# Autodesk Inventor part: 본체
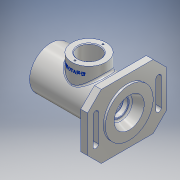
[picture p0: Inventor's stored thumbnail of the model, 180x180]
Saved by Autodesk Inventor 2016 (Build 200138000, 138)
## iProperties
Created: 2017-10
Part Number: 본체
Material: 알루미늄 6061
Document SubType Name: Modeling
Designer: USER
Density: 2.7 g/cm^3
Appearance: 알루미늄 - 평지
Mass: 735.583 g
Surface Area: 651.612 cm^2
Volume: 272.438 cm^3
Author: USER
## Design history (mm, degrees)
sketch "스케치1"
  geometry: L1 (-38, 47)-(38, 47); L2 (58, 27)-(58, -27); L3 (38, -47)-(-38, -47); L4 (-58, -27)-(-58, 27); L5 (-38, 47)-(-58, 27); L6 (38, 47)-(58, 27); L7 (-58, -27)-(-38, -47); L8 (58, -27)-(38, -47); L9 (-46, 20)-(-46, -20); L10 (-50, 20)-(-50, -20); L11 (-42, -20)-(-42, 20); L12 (46, 20)-(46, -20); L13 (42, 20)-(42, -20); L14 (50, -20)-(50, 20); A1 r 4 centre (-46, 20) between (-42, 20) and (-50, 20); A2 r 4 centre (-46, -20) between (-50, -20) and (-42, -20); A3 r 4 centre (46, 20) between (50, 20) and (42, 20); A4 r 4 centre (46, -20) between (42, -20) and (50, -20); 9 further points
  constraints: 32 end point, 8 point on circle, 8 point on line, 8 tangent, 4 centre point, 4 midpoint, 4 parallel, 3 horizontal alignment, 2 vertical, 1 horizontal, 1 perpendicular, 1 vertical alignment
  dimensions: "d4" = 116 distance of point (58, -47) point (-58, -47); "d5" = 94 distance of point (58, 47) point (58, -47); "d6" = 20 distance of L1.start point (-58, 47); "d7" = 20 distance of L4.end point (-58, 47) (= d6); "d8" = 20 distance of L1.end point (58, 47) (= d6); "d9" = 20 distance of L2.start point (58, 47) (= d8); "d10" = 20 distance of L4.start point (-58, -47) (= d6); "d11" = 20 distance of L3.end point (-58, -47) (= d10); "d12" = 20 distance of L2.end point (58, -47) (= d6); "d13" = 20 distance of L3.start point (58, -47) (= d12); "d14" = 8 diameter of A2; "d15" = 20 distance of L9.end point (-46, 0); "d16" = 46 distance of point (0, 0) point (-46, 0); "d18" = 8 diameter of A4; "d19" = 20 distance of L12.end point (46, 0); "d20" = 46 distance of point (0, 0) point (46, 0)
extrude "돌출1" new body sketch "스케치1" distance "d21" = 10; taper "d22" = 0 deg
sketch "스케치2"
  geometry: L1 (-47, 38)-(-47, -38) reference; C1 r 35 at (0, 0); 1 further point
  constraints: 1 centre point, 1 coincident
  dimensions: "d23" = 70 diameter of C1; "d24" = 47 distance from line of C1.centre L1
extrude "돌출2" join sketch "스케치2" distance "d25" = 3; taper "d26" = 0 deg
sketch "스케치3"
  geometry: C1 r 31 at (0, 0); 1 further point
  constraints: 1 centre point, 1 coincident
  dimensions: "d27" = 62 diameter of C1
extrude "돌출3" join sketch "스케치3" distance "d28" = 102; taper "d29" = 0 deg
node "작업 평면1"
sketch "스케치4"
  geometry: L1 (-112, 31)-(-112, -31) reference; L2 (-10, -31)-(-10, 31) reference; L3 (0, 38)-(0, -38) reference; C1 r 25 at (-56, 0); 2 further points
  constraints: 1 centre point, 1 horizontal alignment, 1 midpoint
  dimensions: "d31" = 50 diameter of C1; "d32" = 56 distance from line of C1.centre L1
extrude "돌출4" join sketch "스케치4" stored distance "d33" = 102; taper "d34" = 0 deg
sketch "스케치5"
  geometry: L1 (112, -31)-(112, 31) reference; L2 (10, 31)-(112, 31) reference; L3 (0, 27)-(0, 47) reference; L4 (0, 27)-(10, 27) reference; L5 (10, 47)-(10, 27) reference; L6 (0, 47)-(10, 47) reference; L7 (10, -31)-(112, -31) reference; L8 (0, -47)-(0, -27) reference; L9 (0, -47)-(10, -47) reference; L10 (10, -27)-(10, -47) reference; L11 (0, -27)-(10, -27) reference; L12 (-3, 35)-(-3, -35) reference; L13 (-33.492, 0)-(143.426, 0); L14 (112, 21)-(103, 21); L15 (103, 21)-(103, 24); L16 (103, 24)-(100, 24); L17 (100, 24)-(100, 20); L18 (100, 20)-(91, 20); L19 (91, 20)-(91, 17.5); L20 (91, 17.5)-(87.75, 17.5); L21 (87.75, 17.5)-(87.75, 18.5); L22 (87.75, 18.5)-(86, 18.5); L23 (86, 18.5)-(86, 17.5); L24 (86, 17.5)-(75, 17.5); L25 (75, 17.5)-(75, 26); L26 (75, 26)-(37, 26); L27 (37, 26)-(37, 17.5); L28 (37, 17.5)-(26, 17.5); L29 (26, 17.5)-(26, 17.5); L30 (26, 17.5)-(26, 16.5); L31 (26, 16.5)-(21, 16.5); L32 (21, 16.5)-(21, 10); L33 (21, 10)-(18.3, 10); L34 (18.3, 10)-(18.3, 12.5); L35 (18.3, 12.5)-(11, 12.5); L36 (11, 12.5)-(11, 16); L37 (11, 16)-(-3, 22); L38 (112, 21)-(112, 0); L39 (112, 0)-(-3, 0); L40 (-3, 22)-(-3, 0); 1 further point
  constraints: 56 end point, 19 perpendicular, 7 point on line, 2 horizontal, 2 midpoint, 2 vertical, 1 horizontal alignment
  dimensions: "d35" = 42 diameter of L14 L13; "d36" = 9 distance between parallel lines of L15 L38; "d37" = 3 distance between parallel lines of L17 L15; "d38" = 48 diameter of L16 L13; "d39" = 40 diameter of L18 L13; "d40" = 9 distance between parallel lines of L19 L17; "d41" = 35 diameter of L20 L13; "d42" = 3.25 distance from line of L21.end L19; "d43" = 37 diameter of L22 L13; "d44" = 1.75 distance between parallel lines of L23 L21; "d45" = 11 distance between parallel lines of L25 L23; "d46" = 52 diameter of L26 L13; "d47" = 38 distance between parallel lines of L27 L25; "d48" = 11 distance between parallel lines of L30 L27; "d49" = 5 distance between parallel lines of L32 L30; "d50" = 33 diameter of L31 L13; "d51" = 20 diameter of L33 L13; "d52" = 2.7 distance of L33.end L32.end; "d53" = 7.3 distance between parallel lines of L36 L34; "d54" = 25 diameter of L35 L13; "d55" = 44 diameter of L37.end L13; "d56" = 32 diameter of L36.end L13
revolve "회전1" sketch "스케치5" stored, may be unused: angle "d57" = 90 deg
sketch "스케치6"
  geometry: C1 r 25 at (0, 0) reference; C2 r 16 at (0, 0); 1 further point
  constraints: 1 centre point, 1 coincident
  dimensions: "d58" = 32 diameter of C2
extrude "돌출5" cut sketch "스케치6" stored distance "d59" = 102; taper "d60" = 0 deg
sketch "스케치7"
  geometry: C1 r 16 at (0, 0) reference; C2 r 25 at (0, 0) reference; 2 further points
  constraints: 1 vertical alignment
  dimensions: "d61" = 20.5 distance of C1.centre point (0, 20.5)
hole "구멍1" sketch "스케치7" at (0, 20.5) diameter "d62" = 2.459; stored, may be unused: countersink angle "d66" = 90 deg, drill point angle "d68" = 118 deg; dims "d63" = 6, "d64" = 4, "d65" = 2, "d67" = 8
fillet "모깎기1" dims "d72" = 3
feature "스레드1" dims "d73" = 10, "d74" = 0
chamfer "모따기1" distance "d75" = 1; stored, may be unused: second distance "d76" = 2, angle "d77" = 45 deg
chamfer "모따기2" distance "d78" = 1; stored, may be unused: second distance "d79" = 2, angle "d80" = 45 deg
fillet "모깎기2" dims "d81" = 3
chamfer "모따기3" distance "d82" = 1; stored, may be unused: second distance "d83" = 2, angle "d84" = 45 deg
fillet "모깎기3" dims "d85" = 0.3
fillet "모깎기4" dims "d86" = 3
fillet "모깎기5" dims "d87" = 3
chamfer "모따기4" distance "d88" = 0.7; stored, may be unused: second distance "d89" = 2, angle "d90" = 30 deg
fillet "모깎기6" dims "d91" = 0.3
node "작업 평면4"
sketch "스케치11"
  geometry: L1 (-25, 0)-(25, 0) reference; L2 (56, -78)-(56, -16) reference; 2 further points
  constraints: 1 other
  dimensions: "d97" = 10 distance from line of point (0, -10) L1; "d98" = 56 distance from line of L2 point (0, -10)
feature "엠보싱2" sketch "스케치11" dims "d4" = 116, "d5" = 94, "d6" = 20, "d7" = 20 (= d6), "d8" = 20 (= d6), "d9" = 20 (= d8), "d10" = 20 (= d6), "d11" = 20 (= d10), "d12" = 20 (= d6), "d13" = 20 (= d12), "d14" = 8, "d15" = 20, "d16" = 46, "d99" = 0.5, "d100" = 0
chamfer "모따기5" distance "d101" = 1; stored, may be unused: second distance "d102" = 2, angle "d103" = 45 deg
node "솔리드1"
pattern_circular "원형 패턴1" dims angle "d70" = 360 deg
node "투영된 루프1"
node "투영된 루프2"
node "투영된 루프3"
node "투영된 루프4"
node "투영된 루프5"
other parameters: "d30" = 47
